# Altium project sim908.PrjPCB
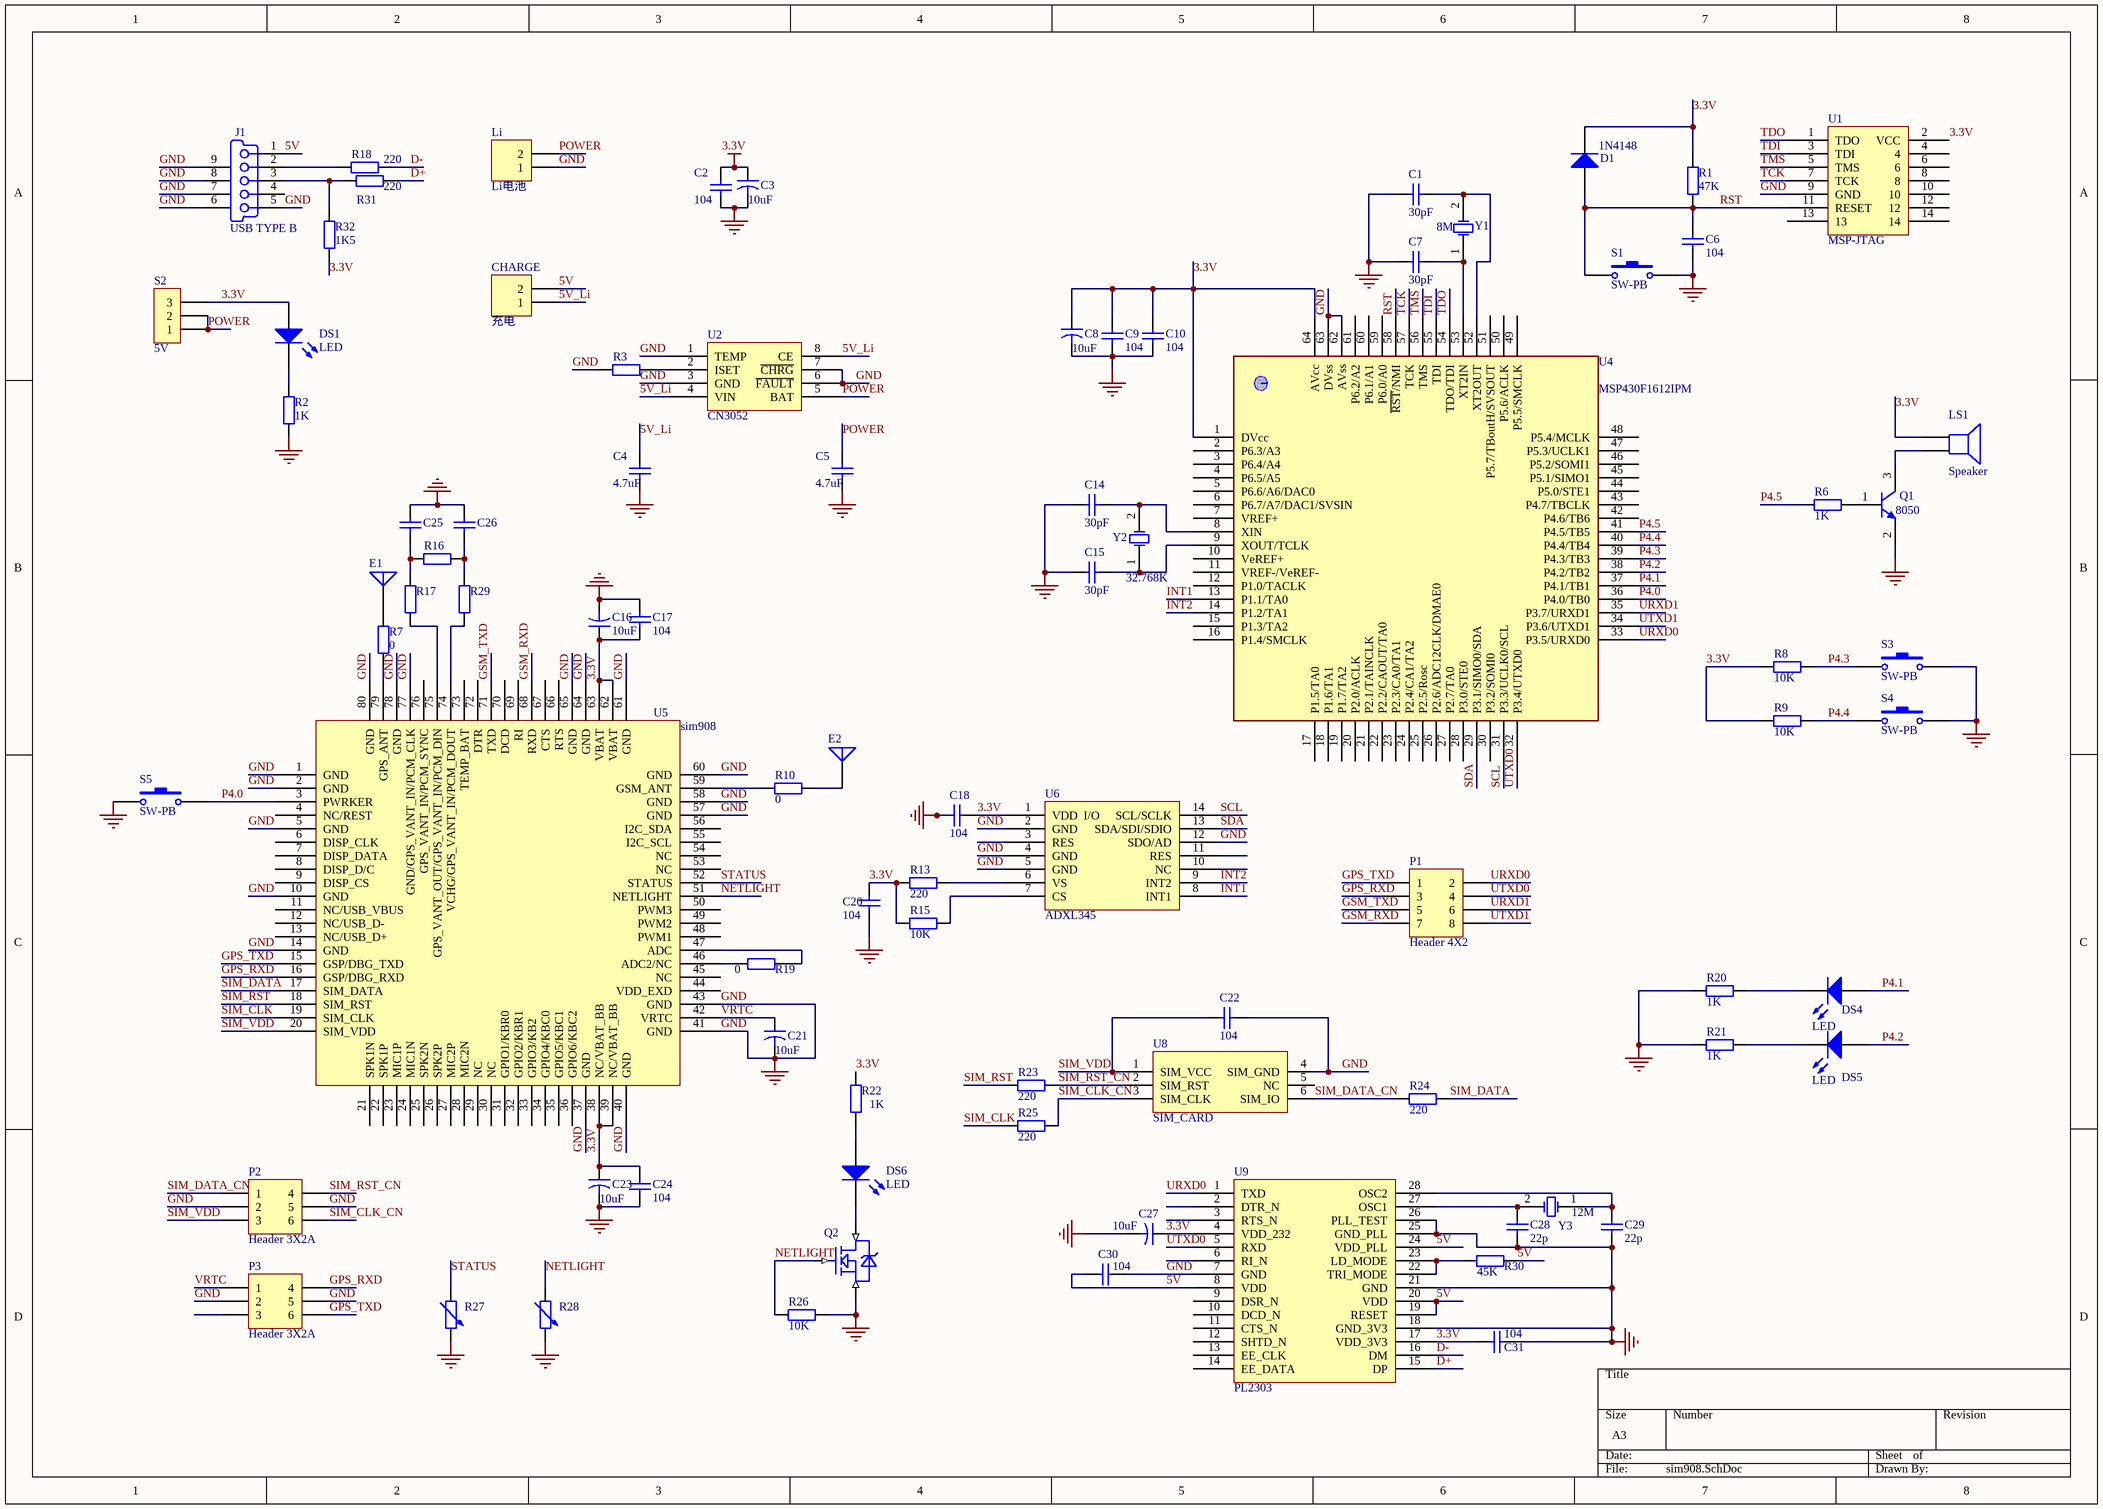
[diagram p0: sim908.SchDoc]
1 sheet, 85 parts. Net scope: global (net labels, ports and power ports of the same name join across sheets).
Board file: sim908.PcbDoc

## Sheet sim908.SchDoc
size A3

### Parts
C1  value 30pF  [C0603]  (hidden comment: Cap)
C2  value 104  [C0603]  (hidden comment: Cap)
C3  value 10uF  [3216C]  (hidden comment: Cap2)
C4  value 4.7uF  [C0603]  (hidden comment: Cap)
C5  value 4.7uF  [C0603]  (hidden comment: Cap)
C6  104  [C0603]
C7  value 30pF  [C0603]  (hidden comment: Cap)
C8  value 10uF  [3216C]  (hidden comment: Cap2)
C9  value 104  [C0603]  (hidden comment: Cap)
C10  value 104  [C0603]  (hidden comment: Cap)
C14  value 30pF  [C0603]  (hidden comment: Cap)
C15  value 30pF  [C0603]  (hidden comment: Cap)
C16  value 10uF  [3216C]  (hidden comment: Cap2)
C17  value 104  [C0603]  (hidden comment: Cap)
C18  value 104  [C0603]  (hidden comment: Cap)
C20  value 104  [C0603]  (hidden comment: Cap)
C21  value 10uF  [3216C]  (hidden comment: Cap2)
C22  value 104  [C0603]  (hidden comment: Cap)
C23  value 10uF  [3216C]  (hidden comment: Cap2)
C24  value 104  [C0603]  (hidden comment: Cap)
C25  Cap  [C0603]  (value not drawn)
C26  Cap  [C0603]  (value not drawn)
C27  value 10uF  [3216C]  (hidden comment: Cap2)
C28  value 22p  [C0603]  (hidden comment: Cap)
C29  value 22p  [C0603]  (hidden comment: Cap)
C30  value 104  [C0603]  (hidden comment: Cap)
C31  value 104  [C0603]  (hidden comment: Cap)
CHARGE  充电  [HDR1X2]
D1  1N4148  [DIODE-1A]
DS1  LED  [LED0603_AB]
DS4  LED  [LED0603_AB]
DS5  LED  [LED0603_AB]
DS6  LED  [LED0603_AB]
E1  Antenna  [GPS天线]  (value not drawn)
E2  Comment  [SMA底座]  (value not drawn)
J1  USB TYPE B  [USB-Small]
Li  Li电池  [HDR1X2]
LS1  Speaker  [BUZZER 7.6mm]
P1  Header 4X2  [HDR2X4]
P2  Header 3X2A  [SOT-23-6]
P3  Header 3X2A  [SOT-23-6]
Q1  8050  [NPN]
Q2  (no value)  [NPN]
R1  value 47K  [R0603]  (hidden comment: Res2)
R2  value 1K  [R0603]  (hidden comment: Res2)
R3  Res2  [R0603]  (value not drawn)
R6  value 1K  [R0603]  (hidden comment: Res2)
R7  value 0  [R0603]  (hidden comment: Res2)
R8  value 10K  [R0603]  (hidden comment: Res2)
R9  value 10K  [R0603]  (hidden comment: Res2)
R10  value 0  [R0603]  (hidden comment: Res2)
R13  value 220  [R0603]  (hidden comment: Res2)
R15  value 10K  [R0603]  (hidden comment: Res2)
R16  Res2  [R0603]  (value not drawn)
R17  Res2  [R0603]  (value not drawn)
R18  value 220  [R0603]  (hidden comment: Res2)
R19  value 0  [R0603]  (hidden comment: Res2)
R20  value 1K  [R0603]  (hidden comment: Res2)
R21  value 1K  [R0603]  (hidden comment: Res2)
R22  value 1K  [R0603]  (hidden comment: Res2)
R23  value 220  [R0603]  (hidden comment: Res2)
R24  value 220  [R0603]  (hidden comment: Res2)
R25  value 220  [R0603]  (hidden comment: Res2)
R26  value 10K  [R0603]  (hidden comment: Res2)
R27  Res Adj2  [R0603]  (value not drawn)
R28  Res Adj2  [R0603]  (value not drawn)
R29  Res2  [R0603]  (value not drawn)
R30  value 45K  [R0603]  (hidden comment: Res2)
R31  value 220  [R0603]  (hidden comment: Res2)
R32  value 1K5  [R0603]  (hidden comment: Res2)
S1  SW-PB  [SWPB2-SMD]
S2  5V  [小拨档开关]
S3  SW-PB  [SWPB2-SMD]
S4  SW-PB  [SWPB2-SMD]
S5  SW-PB  [SWPB2-SMD]
U1  MSP-JTAG  [DIP14]
U2  CN3052  [SO-8]
U4  MSP430F1612IPM  [PM]
U5  sim908  [SIM908]
U6  ADXL345  [ADXL345_1]
U8  SIM_CARD  [SIM卡座]
U9  PL2303  [ssop28]
Y1  8M  [XTAL-0.2]
Y2  32.768K  [OSC1]
Y3  12M  [XTAL-0.2]

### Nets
3.3V: C2.2 C3.1 C8.1 C9.2 C10.2 C16.1 C17.1 C18.1 C20.2 C23.1 C24.2 C27.1 C31.1 D1.2(K) DS1.1(A) LS1.1 R1.2 R8.2 R9.2 R13.1 R15.1 R22.2 R32.2 S2.3 U1.2(VCC) U4.1(DVcc) U4.64(AVcc) U5.38(NC/VBAT_BB) U5.39(NC/VBAT_BB) U5.62(VBAT) U5.63(VBAT) U6.1(VDD__I/O) U9.4(VDD_232) U9.17(VDD_3V3)
GND: C1.1 C2.1 C3.2 C4.1 C5.1 C6.1 C7.1 C8.2 C9.1 C10.1 C14.1 C15.1 C16.2 C17.2 C18.2 C20.1 C21.2 C22.1 C23.2 C24.1 C25.2 C26.2 C27.2 C28.2 C29.2 C30.2 C31.2 J1.5 J1.6 J1.7 J1.8 J1.9 Li.1 P2.2 P2.5 P3.2 P3.5 Q1.2(E) Q2.2(S) R2.2 R3.2 R20.2 R21.2 R26.1 R27.2 R28.2 S1.2 S3.2 S4.2 S5.1 U1.9(GND) U2.1(TEMP) U2.3(GND) U2.6(~{FAULT}) U2.7(~{CHRG}) U4.62(AVss) U4.63(DVss) U5.1(GND) U5.2(GND) U5.5(GND) U5.10(GND) U5.14(GND) U5.37(GND) U5.40(GND) U5.41(GND) U5.43(GND) U5.57(GND) U5.58(GND) U5.60(GND) U5.61(GND) U5.64(GND) U5.65(GND) U5.77(GND/GPS_VANT_IN/PCM_CLK) U5.78(GND) U5.80(GND) U6.2(GND) U6.4(GND) U6.5(GND) U6.12(SDO/AD) U8.4(SIM_GND) U9.7(GND) U9.18(GND_3V3) U9.21(GND) U9.25(GND_PLL) U9.26(PLL_TEST)
5V: C30.1 CHARGE.2 J1.1 R30.1 U9.8(VDD) U9.19(RESET) U9.20(VDD) U9.24(VDD_PLL)
5V_Li: C4.2 CHARGE.1 U2.4(VIN) U2.8(CE)
D+: R31.1 U9.15(DP)
D-: R18.1 U9.16(DM)
GPS_RXD: P1.3 P3.4 U5.16(GSP/DBG_RXD)
GPS_TXD: P1.1 P3.6 U5.15(GSP/DBG_TXD)
GSM_RXD: P1.7 U5.68(RXD)
GSM_TXD: P1.5 U5.71(TXD)
INT1: U4.13(P1.1/TA0) U6.8(INT1)
INT2: U4.14(P1.2/TA1) U6.9(INT2)
NETLIGHT: Q2.1(G) R26.2 R28.1 U5.51(NETLIGHT)
P4.0: S5.2 U4.36(P4.0/TB0) U5.3(PWRKER)
P4.1: DS4.1(A) U4.37(P4.1/TB1)
P4.2: DS5.1(A) U4.38(P4.2/TB2)
P4.3: R8.1 S3.1 U4.39(P4.3/TB3)
P4.4: R9.1 S4.1 U4.40(P4.4/TB4)
P4.5: R6.2 U4.41(P4.5/TB5)
POWER: C5.2 Li.2 S2.1 S2.2 U2.5(BAT)
RST: C6.2 D1.1(A) R1.1 S1.1 U1.11(RESET) U4.58(~{RST}/NMI)
SCL: U4.31(P3.3/UCLK0/SCL) U6.14(SCL/SCLK)
SDA: U4.29(P3.1/SIMO0/SDA) U6.13(SDA/SDI/SDIO)
SIM_CLK: R25.1 U5.19(SIM_CLK)
SIM_CLK_CN: P2.6 R25.2 U8.3(SIM_CLK)
SIM_DATA: R24.2 U5.17(SIM_DATA)
SIM_DATA_CN: P2.1 R24.1 U8.6(SIM_IO)
SIM_RST: R23.1 U5.18(SIM_RST)
SIM_RST_CN: P2.4 R23.2 U8.2(SIM_RST)
SIM_VDD: C22.2 P2.3 U5.20(SIM_VDD) U8.1(SIM_VCC)
STATUS: R27.1 U5.52(STATUS)
TCK: U1.7(TCK) U4.57(TCK)
TDI: U1.3(TDI) U4.55(TDI)
TDO: U1.1(TDO) U4.54(TDO/TDI)
TMS: U1.5(TMS) U4.56(TMS)
URXD0: P1.2 U4.33(P3.5/URXD0) U9.1(TXD)
URXD1: P1.6 U4.35(P3.7/URXD1)
UTXD0: P1.4 U4.32(P3.4/UTXD0) U9.5(RXD)
UTXD1: P1.8 U4.34(P3.6/UTXD1)
VRTC: C21.1 P3.1 U5.42(VRTC)
NetC1_2: C1.2 U4.52(XT2OUT) Y1.2(OSC2)
NetC7_2: C7.2 U4.53(XT2IN) Y1.1(OSC1)
NetC14_2: C14.2 U4.8(XIN) Y2.2(OSC2)
NetC15_2: C15.2 U4.9(XOUT/TCLK) Y2.1(OSC1)
NetC25_1: C25.1 R16.2 R17.2
NetC26_1: C26.1 R16.1 R29.2
NetC28_1: C28.1 U9.27(OSC1) Y3.2(OSC2)
NetC29_1: C29.1 U9.28(OSC2) Y3.1(OSC1)
NetDS1_2: DS1.2(K) R2.1
NetDS4_2: DS4.2(K) R20.1
NetDS5_2: DS5.2(K) R21.1
NetDS6_1: DS6.1(A) R22.1
NetDS6_2: DS6.2(K) Q2.3(D)
NetE1_1: E1.1(A) R7.2
NetE2_1: E2.1(A) R10.2
NetJ1_2: J1.2 R18.2
NetJ1_3: J1.3 R31.2 R32.1
NetLS1_2: LS1.2 Q1.3(C)
NetQ1_1: Q1.1(B) R6.1
NetR3_1: R3.1 U2.2(ISET)
NetR7_1: R7.1 U5.79(GPS_ANT)
NetR10_1: R10.1 U5.59(GSM_ANT)
NetR13_2: R13.2 U6.6(VS)
NetR15_2: R15.2 U6.7(CS)
NetR17_1: R17.1 U5.75(GPS_VANT_OUT/GPS_VANT_IN/PCM_DIN)
NetR19_1: R19.1 U5.46(ADC2/NC)
NetR19_2: R19.2 U5.47(ADC)
NetR29_1: R29.1 U5.74(VCHG/GPS_VANT_IN/PCM_DOUT)
NetR30_2: R30.2 U9.22(TRI_MODE) U9.23(LD_MODE)

Not connected (* = marked no-connect by the designer): J1 4; P3 3; U1 4 6 8 10 12 13 14; U4 2(P6.3/A3) 3(P6.4/A4) 4(P6.5/A5) 5(P6.6/A6/DAC0) 6(P6.7/A7/DAC1/SVSIN) 7(VREF+) 10(VeREF+) 11(VREF-/VeREF-) 12(P1.0/TACLK) 15(P1.3/TA2) 16(P1.4/SMCLK) 17(P1.5/TA0) 18(P1.6/TA1) 19(P1.7/TA2) 20(P2.0/ACLK) 21(P2.1/TAINCLK) 22(P2.2/CAOUT/TA0) 23(P2.3/CA0/TA1) 24(P2.4/CA1/TA2) 25(P2.5/Rosc) 26(P2.6/ADC12CLK/DMAE0) 27(P2.7/TA0) 28(P3.0/STE0) 30(P3.2/SOMI0) 42(P4.6/TB6) 43(P4.7/TBCLK) 44(P5.0/STE1) 45(P5.1/SIMO1) 46(P5.2/SOMI1) 47(P5.3/UCLK1) 48(P5.4/MCLK) 49(P5.5/SMCLK) 50(P5.6/ACLK) 51(P5.7/TBoutH/SVSOUT) 59(P6.0/A0) 60(P6.1/A1) 61(P6.2/A2); U5 4(NC/REST) 6(DISP_CLK) 7(DISP_DATA) 8(DISP_D/C) 9(DISP_CS) 11(NC/USB_VBUS) 12(NC/USB_D-) 13(NC/USB_D+) 21(SPK1N) 22(SPK1P) 23(MIC1P) 24(MIC1N) 25(SPK2N) 26(SPK2P) 27(MIC2P) 28(MIC2N) 29(NC) 30(NC) 31(GPIO1/KBR0) 32(GPIO2/KBR1) 33(GPIO3/KB2) 34(GPIO4/KBC0) 35(GPIO5/KBC1) 36(GPIO6/KBC2) 44(VDD_EXD) 45(NC) 48(PWM1) 49(PWM2) 50(PWM3) 53(NC) 54(NC) 55(I2C_SCL) 56(I2C_SDA) 66(RTS) 67(CTS) 69(RI) 70(DCD) 72(DTR) 73(TEMP_BAT) 76(GPS_VANT_IN/PCM_SYNC); U6 3(RES) 10(NC) 11(RES); U8 5(NC); U9 2(DTR_N) 3(RTS_N) 6(RI_N) 9(DSR_N) 10(DCD_N) 11(CTS_N) 12(SHTD_N) 13(EE_CLK) 14(EE_DATA)

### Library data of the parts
C1 C2 C4-C7 C9 C10 C14 C15 C17 C18 C20 C22 C24 C28-C31 = Cap: Capacitor
C3 C8 C16 C21 C23 C27 = Cap2: Capacitor
C25 C26 = Cap: Capacitor; Value: 104
CHARGE Li = Header 2: Header, 2-Pin
D1 = Diode 1N4148: High Conductance Fast Diode
DS1 DS4-DS6 = LED3: Typical BLUE SiC LED
E1 E2 = Antenna: Generic Antenna
J1 = miniUSB: USB, SMD, Type B, Molex; Connector type: Right Angle; Max Current: mA
LS1 = Speaker: Loudspeaker
P1 = Header 4X2: Header, 4-Pin, Dual row
P2 P3 = Header 3X2A: Header, 3-Pin, Dual row
Q1 = QNPN: NPN Bipolar Transistor
Q2 = IRF540
R1-R3 R6-R10 R13 R15 R18-R26 R30-R32 = Res2: Resistor
R16 R17 R29 = Res2: Resistor; Value: 0
R27 R28 = Res Adj2: Variable Resistor; Value: 1K; Set Position: 0.5
S1 S3-S5 = SW-PB: Switch
S2 = CON3: Connector
U4 = MSP430F1612IPM: MSP430F1611IPM
Y1-Y3 = XTAL: Crystal Oscillator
